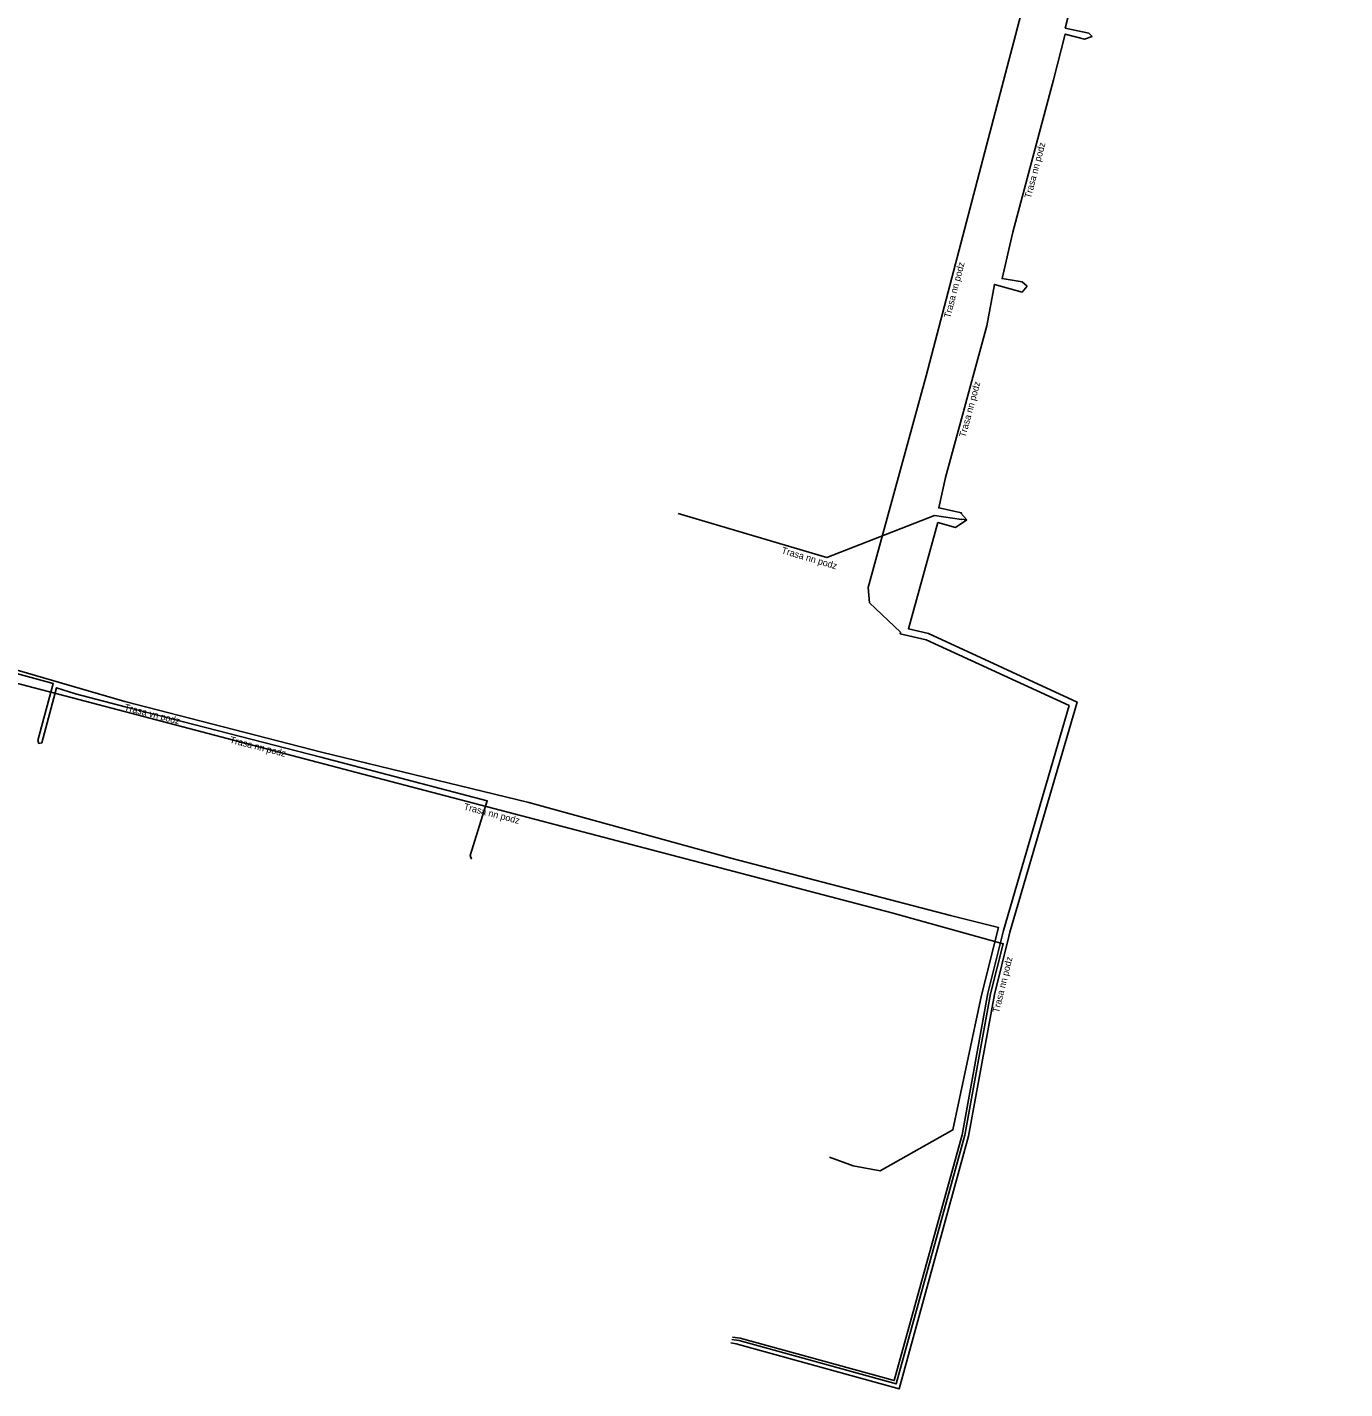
# Model space of a CAD drawing. Extents: x -843786 to -842968, y -1003095 to -1002172.
# Drawn here: x -843355.5 to -843257.4, y -1003000.7 to -1002899.3 of the extents above; entities that cross this region are included whole.
import ezdxf

# ---------------------------------------------------------------- set-up
doc = ezdxf.new("R2010")
doc.units = 0
for name, color, linetype in [('Spojnice NN', 7, 'Continuous'), ('Spojnice VN', 7, 'Continuous'), ('Vrstva 20', 7, 'Continuous')]:
    doc.layers.add(name, color=color, linetype=linetype)

msp = doc.modelspace()

# ---------------------------------------------------------------- linework, layer by layer
at = {"layer": 'Spojnice NN'}
for points in [[(-843257.76, -1002815.63), (-843257.41, -1002816.23), (-843257.61, -1002816.89), (-843262.78, -1002826.99), (-843284.09, -1002908.12), (-843288.58, -1002925.28), (-843292.89, -1002941.02), (-843292.8, -1002942.16), (-843290.49, -1002944.36), (-843290.52, -1002944.47), (-843288.57, -1002944.93), (-843277.94, -1002949.82), (-843282.83, -1002966.55), (-843283.98, -1002971.22), (-843285.91, -1002981.76), (-843290.95, -1003000.05), (-843302.43, -1002996.89), (-843303, -1002996.83)], [(-843269.97, -1002874.47), (-843270.26, -1002874.74), (-843271.83, -1002874.24), (-843272.77, -1002878.01), (-843277.1, -1002894.95), (-843278.23, -1002899.4), (-843276.47, -1002899.78), (-843276.22, -1002900.02)], [(-843276.22, -1002900.02), (-843276.79, -1002900.22), (-843278.23, -1002899.84), (-843279.11, -1002903.23), (-843282.12, -1002914.58), (-843282.93, -1002918.03), (-843281.43, -1002918.28), (-843281.06, -1002918.59)], [(-843281.06, -1002918.59), (-843281.43, -1002919.04), (-843283.5, -1002918.47), (-843284.06, -1002921.55), (-843287.14, -1002932.84), (-843287.64, -1002935.1), (-843285.94, -1002935.47), (-843286.01, -1002935.47), (-843285.55, -1002935.98)], [(-843307.03, -1002935.53), (-843295.98, -1002938.8), (-843287.95, -1002935.66), (-843285.94, -1002935.97), (-843285.95, -1002935.95), (-843285.55, -1002935.98)], [(-843303.11, -1002997.24), (-843302.72, -1002997.33), (-843290.6, -1003000.67), (-843285.42, -1002981.87), (-843283.49, -1002971.33), (-843282.42, -1002967.01), (-843282.34, -1002966.68), (-843277.34, -1002949.55), (-843288.41, -1002944.45), (-843289.9, -1002944.1), (-843287.7, -1002936.2), (-843286.39, -1002936.55), (-843285.55, -1002935.98)], [(-843395.79, -1002943.04), (-843396.58, -1002941.7), (-843396.99, -1002941.55), (-843395.95, -1002937.7), (-843391.01, -1002939.1), (-843352.13, -1002949.25), (-843331, -1002954.79), (-843291.14, -1002965.23), (-843282.84, -1002967.54), (-843283.78, -1002971.27), (-843285.71, -1002981.8), (-843290.81, -1003000.3), (-843302.5, -1002997.08), (-843303.04, -1002997)], [(-843354.64, -1002952.65), (-843354.71, -1002952.42), (-843353.56, -1002948.18), (-843363.6, -1002945.44), (-843369.36, -1002943.89), (-843370.45, -1002948.11), (-843370.69, -1002948.22)], [(-843322.42, -1002961.25), (-843322.53, -1002960.98), (-843321.26, -1002956.91), (-843333.64, -1002953.65), (-843348.2, -1002949.92), (-843351.9, -1002948.93), (-843353.32, -1002948.49), (-843354.42, -1002952.59), (-843354.64, -1002952.65)]]:
    msp.add_lwpolyline(points, dxfattribs=at)
at = {"layer": 'Spojnice VN'}
msp.add_lwpolyline([(-843409.28, -1002966.63), (-843404.85, -1002950.05), (-843402.07, -1002940.71), (-843400.7, -1002936.03), (-843399.91, -1002935.49), (-843394.72, -1002936.79), (-843378.96, -1002940.83), (-843363.52, -1002945.08), (-843348.23, -1002949.51), (-843333.59, -1002953.29), (-843318.16, -1002957.04), (-843303.02, -1002961.19), (-843286.77, -1002965.44), (-843283.2, -1002966.33), (-843284.47, -1002971.37), (-843286.59, -1002981.4), (-843292, -1002984.45), (-843294.02, -1002984.07), (-843295.78, -1002983.43)], dxfattribs=at)

# ---------------------------------------------------------------- texts
at = {"layer": 'Vrstva 20'}
for s, rotation, p in [('Trasa nn podz', 75.1493, (-843280.79, -1002912.1)), ('Trasa nn podz', 75.3389, (-843286.79, -1002921.01)), ('Trasa nn podz', 74.7689, (-843285.66, -1002929.89)), ('Trasa nn podz', 343.5103, (-843299.39, -1002938.47)), ('Trasa vn podz', 345.5328, (-843348.31, -1002950.16)), ('Trasa nn podz', 345.6333, (-843340.46, -1002952.58)), ('Trasa nn podz', 345.3202, (-843323.04, -1002957.55)), ('Trasa nn podz', 76.1587, (-843283.16, -1002972.72))]:
    msp.add_text(s, height=0.5, rotation=rotation, dxfattribs=at).set_placement(p)

doc.saveas('drawing.dxf')
